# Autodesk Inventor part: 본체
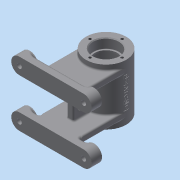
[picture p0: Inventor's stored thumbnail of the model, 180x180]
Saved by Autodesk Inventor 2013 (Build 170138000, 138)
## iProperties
Created: 2015-11
Part Number: 본체
Material: 일반
Document SubType Name: Modeling
Designer: a
Density: 1 g/cm^3
Author: a
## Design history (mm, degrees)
sketch "스케치1"
  geometry: C1 r 25 at (0, 0); 1 further point
  constraints: 1 centre point, 1 coincident
  dimensions: "d0" = 50 diameter of C1
extrude "돌출1" new body sketch "스케치1" stored distance "d1" = 70; taper "d2" = 0 deg
sketch "스케치2"
  geometry: C1 r 21 at (0, 0); 1 further point
  constraints: 1 centre point, 1 coincident
  dimensions: "d3" = 42 diameter of C1
extrude "돌출2" cut sketch "스케치2" stored distance "d4" = 42; taper "d5" = 0 deg
node "작업 평면1"
sketch "스케치3"
  geometry: L1 (40, 20)-(-40, 20); L2 (-50, 30)-(-50, 30); L3 (-40, 40)-(40, 40); L4 (50, 30)-(50, 30); A1 r 10 centre (40, 30) between (40, 20) and (50, 30); A2 r 10 centre (40, 30) between (50, 30) and (40, 40); A3 r 10 centre (-40, 30) between (-40, 40) and (-50, 30); A4 r 10 centre (-40, 30) between (-50, 30) and (-40, 20); 5 further points
  constraints: 8 end point, 8 point on circle, 8 tangent, 6 point on line, 4 centre point, 3 equal radius, 2 parallel, 1 horizontal, 1 midpoint, 1 perpendicular, 1 vertical alignment
  dimensions: "d7" = 100 distance of point (-50, 40) point (50, 40); "d8" = 20 distance of point (-50, 20) point (-50, 40); "d9" = 40 distance from line of point (0, 0) L3; "d10" = 10 radius of A1
extrude "돌출3" join sketch "스케치3" distance "d11" = 10; taper "d12" = 0 deg
sketch "스케치4"
  geometry: C1 r 10 at (-40, -30); C2 r 10 at (40, -30); A1 r 10 centre (-40, -30) between (-40, -20) and (-40, -40) reference; A2 r 10 centre (40, -30) between (40, -40) and (40, -20) reference; 1 further point
  constraints: 2 centre point, 2 coincident
  dimensions: "d13" = 20 diameter of C1; "d14" = 20 diameter of C2
extrude "돌출4" join sketch "스케치4" distance "d15" = 3; taper "d16" = 0 deg
sketch "스케치5"
  geometry: L1 (-25, -20)-(25, -20); L2 (25, -20)-(25, -28); L3 (25, -28)-(-25, -28); L4 (-25, -28)-(-25, -20); 2 further points
  constraints: 8 end point, 2 parallel, 1 horizontal, 1 midpoint, 1 perpendicular, 1 vertical alignment
  dimensions: "d17" = 50 distance of L2.end L3.end; "d18" = 8 distance of L1.end L2.end; "d19" = 20 distance from line of point (0, 0) L1
extrude "돌출5" join sketch "스케치5" stored distance "d20" = 3; taper "d21" = 0 deg
sketch "스케치6"
  geometry: L1 (-45, 20)-(-45, -20); L2 (-21, -21)-(21, -21) reference; L3 (21, -21)-(21, 21) reference; L4 (21, 21)-(-21, 21) reference; L5 (-21, 21)-(-21, -21) reference; L6 (25, 35)-(25, -35) reference; L7 (25, -35)-(-25, -35) reference; L8 (-25, -35)-(-25, -28) reference; L9 (-25, -28)-(-58, -28) reference; L10 (-58, -28)-(-58, -40) reference; L11 (-58, -40)-(-68, -40) reference; L12 (-68, -40)-(-68, -20) reference; L13 (-68, -20)-(-25, -20) reference; L14 (-25, -20)-(-25, 20) reference; L15 (-25, 20)-(-68, 20) reference; L16 (-68, 20)-(-68, 40) reference; L17 (-68, 40)-(-58, 40) reference; L18 (-58, 40)-(-58, 28) reference; L19 (-58, 28)-(-25, 28) reference; L20 (-25, 28)-(-25, 35) reference; L21 (-25, 35)-(25, 35) reference; 2 further points
  constraints: 2 end point, 2 point on line, 1 horizontal alignment, 1 midpoint, 1 vertical
  dimensions: "d22" = 20 distance between parallel lines of L8 L1
feature "리브1" sketch "스케치6" dims "d23" = 1, "d24" = 8, "d25" = 0, "d26" = 0, "d27" = 1, "d28" = 1
sketch "스케치7"
  geometry: L1 (-12, 6.5)-(-28, 6.5); L2 (-31.5, 10)-(-31.5, 10); L3 (-28, 13.5)-(-12, 13.5); L4 (-8.5, 10)-(-8.5, 10); L5 (-8.5, 6.5)-(-31.5, 13.5); L6 (-31.5, 6.5)-(-8.5, 13.5); L7 (20, -23)-(0, -23) reference; A1 r 3.5 centre (-28, 10) between (-28, 13.5) and (-31.5, 10); A2 r 3.5 centre (-28, 10) between (-31.5, 10) and (-28, 6.5); A3 r 3.5 centre (-12, 10) between (-12, 6.5) and (-8.5, 10); A4 r 3.5 centre (-12, 10) between (-8.5, 10) and (-12, 13.5); 3 further points
  constraints: 12 end point, 8 point on circle, 8 point on line, 8 tangent, 4 centre point, 3 equal radius, 3 midpoint, 2 parallel, 1 horizontal, 1 perpendicular, 1 vertical alignment
  dimensions: "d29" = 23 distance of L5.end L6.end; "d30" = 7 distance of L6.start L5.end; "d31" = 33 distance from line of L7 point (-20, 10); "d32" = 3.5 radius of A1
extrude "돌출6" cut sketch "스케치7" stored distance "d33" = 3; taper "d34" = 0 deg
node "작업 평면2"
sketch "스케치8"
  geometry: C1 r 5 at (0, 0); 1 further point
  constraints: 1 centre point, 1 coincident
  dimensions: "d36" = 10 diameter of C1
extrude "돌출7" join sketch "스케치8" stored distance "d37" = 3; taper "d38" = 0 deg
sketch "스케치9"
  geometry: C1 r 5 at (0, 0) reference
hole "구멍1" sketch "스케치9" at (0, 0) diameter "d39" = 5.188; stored, may be unused: countersink angle "d43" = 90 deg, drill point angle "d45" = 118 deg; dims "d40" = 30, "d41" = 4, "d42" = 2, "d44" = 8
sketch "스케치10"
  geometry: C1 r 25 at (0, 0) reference
hole "구멍2" sketch "스케치10" at (0, 0) diameter "d46" = 28; stored, may be unused: countersink angle "d50" = 90 deg, drill point angle "d52" = 118 deg; dims "d47" = 6, "d48" = 32, "d49" = 12, "d51" = 8
sketch "스케치11"
  geometry: C1 r 16 at (0, 0) reference; 1 further point
  constraints: 1 vertical alignment
  dimensions: "d53" = 20 distance of point (0, 20) C1.centre
hole "구멍3" sketch "스케치11" at (0, 20) diameter "d54" = 3.242; stored, may be unused: countersink angle "d58" = 90 deg, drill point angle "d60" = 118 deg; dims "d55" = 8, "d56" = 10, "d57" = 12, "d59" = 10
sketch "스케치12"
  geometry: L1 (0, 0)-(-14, -24.249); L2 (0, 0)-(28, 0)
  constraints: 4 end point, 1 equal length, 1 horizontal
  dimensions: "d64" = 28 distance of L1.start L1.end; "d65" = 120 deg angle of L1 L2
node "작업 평면3"
sketch "스케치13"
  geometry: C1 r 6 at (0, 0); 1 further point
  constraints: 1 centre point, 1 coincident
  dimensions: "d66" = 12 diameter of C1
extrude "돌출8" join sketch "스케치13" stored distance "d67" = 3; taper "d68" = 0 deg
sketch "스케치14"
  geometry: C1 r 6 at (0, 0) reference
hole "구멍4" sketch "스케치14" at (0, 0) diameter "d69" = 5.188; stored, may be unused: countersink angle "d73" = 90 deg, drill point angle "d75" = 0 deg; dims "d70" = 30, "d71" = 10, "d72" = 12, "d74" = 10
fillet "모깎기1" dims "d76" = 2
fillet "모깎기2" dims "d77" = 2
node "작업 평면4"
sketch "스케치15"
  geometry: L1 (-25, -35)-(-25, 35) reference; L2 (-25, -35)-(25, -35) reference; L3 (25, 35)-(-25, 35) reference; L4 (25, -35)-(25, 35) reference; 2 further points
  constraints: 1 other
  dimensions: "d79" = 35 distance from line of point (0, 0) L2; "d80" = 25 distance from line of L1 point (0, 0); "d96" = 25 distance from line of L4 point (0, 0) (derived); "d97" = 35 distance from line of L3 point (0, 0) (derived)
feature "엠보싱1" sketch "스케치15" dims "d7" = 100, "d8" = 20, "d9" = 40, "d10" = 10, "d81" = 0.5, "d82" = 0
sketch "스케치16"
  geometry: C1 r 10 at (0, 0) reference; C2 r 10 at (0, 60) reference; C3 r 10 at (80, 60) reference; C4 r 10 at (80, 0) reference; 5 further points
  constraints: 4 coincident
hole "구멍5" sketch "스케치16" at (0, 0), (0, 60), (80, 0), (80, 60) diameter "d83" = 6; stored, may be unused: countersink angle "d87" = 90 deg, drill point angle "d89" = 0 deg; dims "d84" = 30, "d85" = 12, "d86" = 4, "d88" = 10
fillet "모깎기3" dims "d90" = 0.3, "d91" = 3
chamfer "모따기1" distance "d92" = 1; stored, may be unused: second distance "d93" = 2, angle "d94" = 45 deg
fillet "모깎기4" dims "d95" = 3
node "솔리드1"
mirror "대칭1"
mirror "대칭2"
mirror "대칭3"
pattern_circular "원형 패턴1" dims angle "d62" = 360 deg
mirror "대칭4"
node "투영된 루프1"
node "투영된 루프2"
node "투영된 루프3"
node "절단 모서리 투영1"
other parameters: "d6" = -68, "d35" = 28, "d78" = 25
